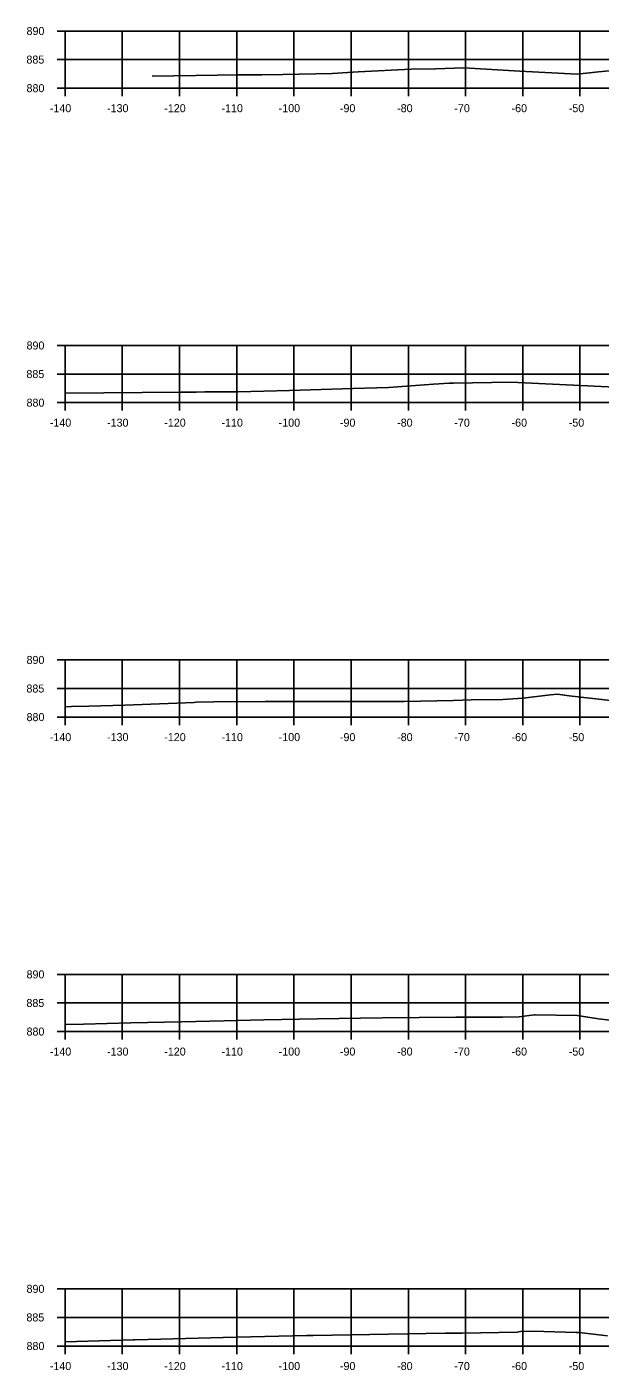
# Model space of a CAD drawing. Extents: x 1098669 to 1198896, y 698679 to 704410.
# Drawn here: x 1113352.2 to 1113452.4, y 701454.3 to 701689.3 of the extents above; entities that cross this region are included whole.
import ezdxf

# ---------------------------------------------------------------- set-up
doc = ezdxf.new("R2010")
doc.units = 0
for name, color, linetype in [('R_Alt Surface', 7, 'Continuous'), ('R_Axis', 7, 'Continuous'), ('R_Axis Annot', 7, 'Continuous'), ('R_Grid', 7, 'Continuous')]:
    doc.layers.add(name, color=color, linetype=linetype)

msp = doc.modelspace()

# ---------------------------------------------------------------- linework, layer by layer
at = {"layer": 'R_Alt Surface'}
for points in [[(1113374.11, 701680.67), (1113385.5, 701680.85), (1113388.91, 701680.91), (1113393.27, 701680.9), (1113396.91, 701680.98), (1113405.56, 701681.15), (1113410.12, 701681.39), (1113419.38, 701681.9), (1113423.61, 701681.96), (1113428.58, 701682.12), (1113438.34, 701681.55), (1113448.36, 701681.01), (1113452.11, 701681.41), (1113456.41, 701681.82)], [(1113358.87, 701625.2), (1113379.11, 701625.37), (1113381.77, 701625.38), (1113383.29, 701625.43), (1113384.99, 701625.47), (1113389.14, 701625.46), (1113398.09, 701625.66), (1113409.18, 701626.04), (1113415.39, 701626.19), (1113423.24, 701626.78), (1113425.98, 701626.97), (1113426.78, 701626.99), (1113436.81, 701627.15), (1113455.01, 701626.27)], [(1113358.87, 701570.38), (1113359.99, 701570.39), (1113363.05, 701570.47), (1113369.34, 701570.67), (1113381.46, 701571.13), (1113381.76, 701571.16), (1113384.89, 701571.21), (1113393.84, 701571.26), (1113399.49, 701571.3), (1113399.75, 701571.3), (1113399.85, 701571.3), (1113416.03, 701571.26), (1113416.51, 701571.28), (1113418.12, 701571.28), (1113426.68, 701571.46), (1113429.87, 701571.6), (1113435.41, 701571.63), (1113438.88, 701571.87), (1113443.7, 701572.47), (1113444.94, 701572.56), (1113446.98, 701572.3), (1113454.74, 701571.43)], [(1113358.87, 701514.78), (1113362.12, 701514.87), (1113370.38, 701515.09), (1113379.21, 701515.26), (1113386.67, 701515.44), (1113393.6, 701515.61), (1113402.97, 701515.78), (1113414.27, 701515.97), (1113427.16, 701516.05), (1113435.3, 701516.06), (1113438.25, 701516.12), (1113440.84, 701516.49), (1113440.86, 701516.49), (1113440.96, 701516.49), (1113448.36, 701516.38), (1113452.08, 701515.81), (1113454.15, 701515.58)], [(1113358.87, 701459.32), (1113370.75, 701459.65), (1113371.03, 701459.66), (1113375.61, 701459.77), (1113386.5, 701460.04), (1113401.07, 701460.4), (1113402.26, 701460.43), (1113425.28, 701460.82), (1113427.1, 701460.83), (1113428.27, 701460.83), (1113437.89, 701461), (1113438.48, 701461.08), (1113440.67, 701461.14), (1113448.21, 701460.91), (1113448.53, 701460.91), (1113448.72, 701460.91), (1113450.73, 701460.67), (1113453.7, 701460.34)]]:
    msp.add_lwpolyline(points, dxfattribs=at)
at = {"layer": 'R_Axis'}
for p, q in [((1113357.47, 701688.56), (1113358.87, 701688.56)), ((1113358.87, 701678.56), (1113358.87, 701688.56)), ((1113357.47, 701683.56), (1113358.87, 701683.56)), ((1113357.47, 701678.56), (1113358.87, 701678.56)), ((1113358.87, 701678.56), (1113638.87, 701678.56)), ((1113358.87, 701677.16), (1113358.87, 701678.56)), ((1113368.87, 701677.16), (1113368.87, 701678.56)), ((1113378.87, 701677.16), (1113378.87, 701678.56)), ((1113388.87, 701677.16), (1113388.87, 701678.56)), ((1113398.87, 701677.16), (1113398.87, 701678.56)), ((1113408.87, 701677.16), (1113408.87, 701678.56)), ((1113418.87, 701677.16), (1113418.87, 701678.56)), ((1113428.87, 701677.16), (1113428.87, 701678.56)), ((1113438.87, 701677.16), (1113438.87, 701678.56)), ((1113448.87, 701677.16), (1113448.87, 701678.56)), ((1113357.47, 701633.56), (1113358.87, 701633.56)), ((1113358.87, 701623.56), (1113358.87, 701633.56)), ((1113357.47, 701628.56), (1113358.87, 701628.56)), ((1113357.47, 701623.56), (1113358.87, 701623.56)), ((1113358.87, 701623.56), (1113638.87, 701623.56)), ((1113358.87, 701622.16), (1113358.87, 701623.56)), ((1113368.87, 701622.16), (1113368.87, 701623.56)), ((1113378.87, 701622.16), (1113378.87, 701623.56)), ((1113388.87, 701622.16), (1113388.87, 701623.56)), ((1113398.87, 701622.16), (1113398.87, 701623.56)), ((1113408.87, 701622.16), (1113408.87, 701623.56)), ((1113418.87, 701622.16), (1113418.87, 701623.56)), ((1113428.87, 701622.16), (1113428.87, 701623.56)), ((1113438.87, 701622.16), (1113438.87, 701623.56)), ((1113448.87, 701622.16), (1113448.87, 701623.56)), ((1113357.47, 701578.56), (1113358.87, 701578.56)), ((1113358.87, 701568.56), (1113358.87, 701578.56)), ((1113357.47, 701573.56), (1113358.87, 701573.56)), ((1113357.47, 701568.56), (1113358.87, 701568.56)), ((1113358.87, 701568.56), (1113638.87, 701568.56)), ((1113358.87, 701567.16), (1113358.87, 701568.56)), ((1113368.87, 701567.16), (1113368.87, 701568.56)), ((1113378.87, 701567.16), (1113378.87, 701568.56)), ((1113388.87, 701567.16), (1113388.87, 701568.56)), ((1113398.87, 701567.16), (1113398.87, 701568.56)), ((1113408.87, 701567.16), (1113408.87, 701568.56)), ((1113418.87, 701567.16), (1113418.87, 701568.56)), ((1113428.87, 701567.16), (1113428.87, 701568.56)), ((1113438.87, 701567.16), (1113438.87, 701568.56)), ((1113448.87, 701567.16), (1113448.87, 701568.56)), ((1113357.47, 701523.56), (1113358.87, 701523.56)), ((1113358.87, 701513.56), (1113358.87, 701523.56)), ((1113357.47, 701518.56), (1113358.87, 701518.56)), ((1113357.47, 701513.56), (1113358.87, 701513.56)), ((1113358.87, 701513.56), (1113638.87, 701513.56)), ((1113358.87, 701512.16), (1113358.87, 701513.56)), ((1113368.87, 701512.16), (1113368.87, 701513.56)), ((1113378.87, 701512.16), (1113378.87, 701513.56)), ((1113388.87, 701512.16), (1113388.87, 701513.56)), ((1113398.87, 701512.16), (1113398.87, 701513.56)), ((1113408.87, 701512.16), (1113408.87, 701513.56)), ((1113418.87, 701512.16), (1113418.87, 701513.56)), ((1113428.87, 701512.16), (1113428.87, 701513.56)), ((1113438.87, 701512.16), (1113438.87, 701513.56)), ((1113448.87, 701512.16), (1113448.87, 701513.56)), ((1113357.47, 701468.56), (1113358.87, 701468.56)), ((1113358.87, 701458.56), (1113358.87, 701468.56)), ((1113357.47, 701463.56), (1113358.87, 701463.56)), ((1113357.47, 701458.56), (1113358.87, 701458.56)), ((1113358.87, 701458.56), (1113638.87, 701458.56)), ((1113358.87, 701457.16), (1113358.87, 701458.56)), ((1113368.87, 701457.16), (1113368.87, 701458.56)), ((1113378.87, 701457.16), (1113378.87, 701458.56)), ((1113388.87, 701457.16), (1113388.87, 701458.56)), ((1113398.87, 701457.16), (1113398.87, 701458.56)), ((1113408.87, 701457.16), (1113408.87, 701458.56)), ((1113418.87, 701457.16), (1113418.87, 701458.56)), ((1113428.87, 701457.16), (1113428.87, 701458.56)), ((1113438.87, 701457.16), (1113438.87, 701458.56)), ((1113448.87, 701457.16), (1113448.87, 701458.56))]:
    msp.add_line(p, q, dxfattribs=at)
at = {"layer": 'R_Grid'}
for p, q in [((1113358.87, 701688.56), (1113638.87, 701688.56)), ((1113358.87, 701678.56), (1113358.87, 701688.56)), ((1113368.87, 701678.56), (1113368.87, 701688.56)), ((1113378.87, 701678.56), (1113378.87, 701688.56)), ((1113388.87, 701678.56), (1113388.87, 701688.56)), ((1113398.87, 701678.56), (1113398.87, 701688.56)), ((1113408.87, 701678.56), (1113408.87, 701688.56)), ((1113418.87, 701678.56), (1113418.87, 701688.56)), ((1113428.87, 701678.56), (1113428.87, 701688.56)), ((1113438.87, 701678.56), (1113438.87, 701688.56)), ((1113448.87, 701678.56), (1113448.87, 701688.56)), ((1113358.87, 701683.56), (1113638.87, 701683.56)), ((1113358.87, 701678.56), (1113638.87, 701678.56)), ((1113358.87, 701633.56), (1113638.87, 701633.56)), ((1113358.87, 701623.56), (1113358.87, 701633.56)), ((1113368.87, 701623.56), (1113368.87, 701633.56)), ((1113378.87, 701623.56), (1113378.87, 701633.56)), ((1113388.87, 701623.56), (1113388.87, 701633.56)), ((1113398.87, 701623.56), (1113398.87, 701633.56)), ((1113408.87, 701623.56), (1113408.87, 701633.56)), ((1113418.87, 701623.56), (1113418.87, 701633.56)), ((1113428.87, 701623.56), (1113428.87, 701633.56)), ((1113438.87, 701623.56), (1113438.87, 701633.56)), ((1113448.87, 701623.56), (1113448.87, 701633.56)), ((1113358.87, 701628.56), (1113638.87, 701628.56)), ((1113358.87, 701623.56), (1113638.87, 701623.56)), ((1113358.87, 701578.56), (1113638.87, 701578.56)), ((1113358.87, 701568.56), (1113358.87, 701578.56)), ((1113368.87, 701568.56), (1113368.87, 701578.56)), ((1113378.87, 701568.56), (1113378.87, 701578.56)), ((1113388.87, 701568.56), (1113388.87, 701578.56)), ((1113398.87, 701568.56), (1113398.87, 701578.56)), ((1113408.87, 701568.56), (1113408.87, 701578.56)), ((1113418.87, 701568.56), (1113418.87, 701578.56)), ((1113428.87, 701568.56), (1113428.87, 701578.56)), ((1113438.87, 701568.56), (1113438.87, 701578.56)), ((1113448.87, 701568.56), (1113448.87, 701578.56)), ((1113358.87, 701573.56), (1113638.87, 701573.56)), ((1113358.87, 701568.56), (1113638.87, 701568.56)), ((1113358.87, 701523.56), (1113638.87, 701523.56)), ((1113358.87, 701513.56), (1113358.87, 701523.56)), ((1113368.87, 701513.56), (1113368.87, 701523.56)), ((1113378.87, 701513.56), (1113378.87, 701523.56)), ((1113388.87, 701513.56), (1113388.87, 701523.56)), ((1113398.87, 701513.56), (1113398.87, 701523.56)), ((1113408.87, 701513.56), (1113408.87, 701523.56)), ((1113418.87, 701513.56), (1113418.87, 701523.56)), ((1113428.87, 701513.56), (1113428.87, 701523.56)), ((1113438.87, 701513.56), (1113438.87, 701523.56)), ((1113448.87, 701513.56), (1113448.87, 701523.56)), ((1113358.87, 701518.56), (1113638.87, 701518.56)), ((1113358.87, 701513.56), (1113638.87, 701513.56)), ((1113358.87, 701468.56), (1113638.87, 701468.56)), ((1113358.87, 701458.56), (1113358.87, 701468.56)), ((1113368.87, 701458.56), (1113368.87, 701468.56)), ((1113378.87, 701458.56), (1113378.87, 701468.56)), ((1113388.87, 701458.56), (1113388.87, 701468.56)), ((1113398.87, 701458.56), (1113398.87, 701468.56)), ((1113408.87, 701458.56), (1113408.87, 701468.56)), ((1113418.87, 701458.56), (1113418.87, 701468.56)), ((1113428.87, 701458.56), (1113428.87, 701468.56)), ((1113438.87, 701458.56), (1113438.87, 701468.56)), ((1113448.87, 701458.56), (1113448.87, 701468.56)), ((1113358.87, 701463.56), (1113638.87, 701463.56)), ((1113358.87, 701458.56), (1113638.87, 701458.56))]:
    msp.add_line(p, q, dxfattribs=at)

# ---------------------------------------------------------------- texts
at = {"layer": 'R_Axis Annot'}
for s, p in [('890', (1113352.14, 701687.86)), ('885', (1113352.12, 701682.86)), ('880', (1113352.14, 701677.86)), ('-140', (1113356.21, 701674.36)), ('-130', (1113366.21, 701674.36)), ('-120', (1113376.21, 701674.36)), ('-110', (1113386.21, 701674.36)), ('-100', (1113396.21, 701674.36)), ('-90', (1113406.91, 701674.36)), ('-80', (1113416.91, 701674.36)), ('-70', (1113426.91, 701674.36)), ('-60', (1113436.91, 701674.36)), ('-50', (1113446.91, 701674.36)), ('890', (1113352.14, 701632.86)), ('885', (1113352.12, 701627.86)), ('880', (1113352.14, 701622.86)), ('-140', (1113356.21, 701619.36)), ('-130', (1113366.21, 701619.36)), ('-120', (1113376.21, 701619.36)), ('-110', (1113386.21, 701619.36)), ('-100', (1113396.21, 701619.36)), ('-90', (1113406.91, 701619.36)), ('-80', (1113416.91, 701619.36)), ('-70', (1113426.91, 701619.36)), ('-60', (1113436.91, 701619.36)), ('-50', (1113446.91, 701619.36)), ('890', (1113352.14, 701577.86)), ('885', (1113352.12, 701572.86)), ('880', (1113352.14, 701567.86)), ('-140', (1113356.21, 701564.36)), ('-130', (1113366.21, 701564.36)), ('-120', (1113376.21, 701564.36)), ('-110', (1113386.21, 701564.36)), ('-100', (1113396.21, 701564.36)), ('-90', (1113406.91, 701564.36)), ('-80', (1113416.91, 701564.36)), ('-70', (1113426.91, 701564.36)), ('-60', (1113436.91, 701564.36)), ('-50', (1113446.91, 701564.36)), ('890', (1113352.14, 701522.86)), ('885', (1113352.12, 701517.86)), ('880', (1113352.14, 701512.86)), ('-140', (1113356.21, 701509.36)), ('-130', (1113366.21, 701509.36)), ('-120', (1113376.21, 701509.36)), ('-110', (1113386.21, 701509.36)), ('-100', (1113396.21, 701509.36)), ('-90', (1113406.91, 701509.36)), ('-80', (1113416.91, 701509.36)), ('-70', (1113426.91, 701509.36)), ('-60', (1113436.91, 701509.36)), ('-50', (1113446.91, 701509.36)), ('890', (1113352.14, 701467.86)), ('885', (1113352.12, 701462.86)), ('880', (1113352.14, 701457.86)), ('-140', (1113356.21, 701454.36)), ('-130', (1113366.21, 701454.36)), ('-120', (1113376.21, 701454.36)), ('-110', (1113386.21, 701454.36)), ('-100', (1113396.21, 701454.36)), ('-90', (1113406.91, 701454.36)), ('-80', (1113416.91, 701454.36)), ('-70', (1113426.91, 701454.36)), ('-60', (1113436.91, 701454.36)), ('-50', (1113446.91, 701454.36))]:
    msp.add_text(s, height=1.4, dxfattribs=at).set_placement(p)

doc.saveas('drawing.dxf')
